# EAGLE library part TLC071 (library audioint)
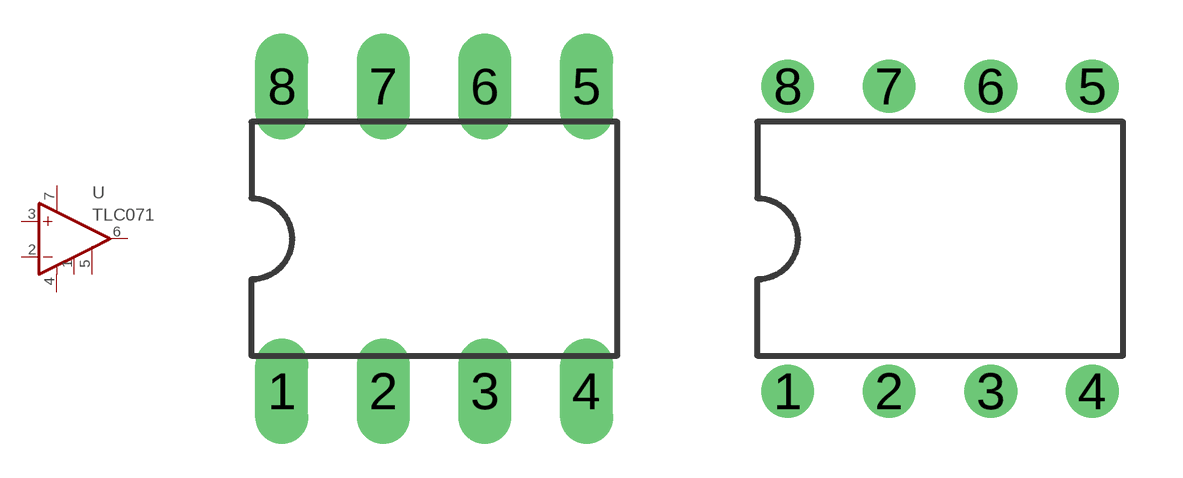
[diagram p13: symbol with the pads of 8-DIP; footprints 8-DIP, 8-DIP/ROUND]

Designator prefix -

## TLC0718-DIP  [8-DIP]
1  OFF+
2  -IN  in
3  +IN  in
4  V-  pwr
5  OFF-
6  OUT  out
7  V+  pwr

## TLC0718-DIP/ROUND  [8-DIP/ROUND]
Pads as for 8-DIP

## Footprint 8-DIP (pad centres in mm)
drill 0.813 long: 1 -3.81,-3.81; 2 -1.27,-3.81; 3 1.27,-3.81; 4 3.81,-3.81; 5 3.81,3.81; 6 1.27,3.81; 7 -1.27,3.81; 8 -3.81,3.81

## Footprint 8-DIP/ROUND (pad centres in mm)
drill 0.813 pad 1.321 round: 1 -3.81,-3.81; 2 -1.27,-3.81; 3 1.27,-3.81; 4 3.81,-3.81; 5 3.81,3.81; 6 1.27,3.81; 7 -1.27,3.81; 8 -3.81,3.81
